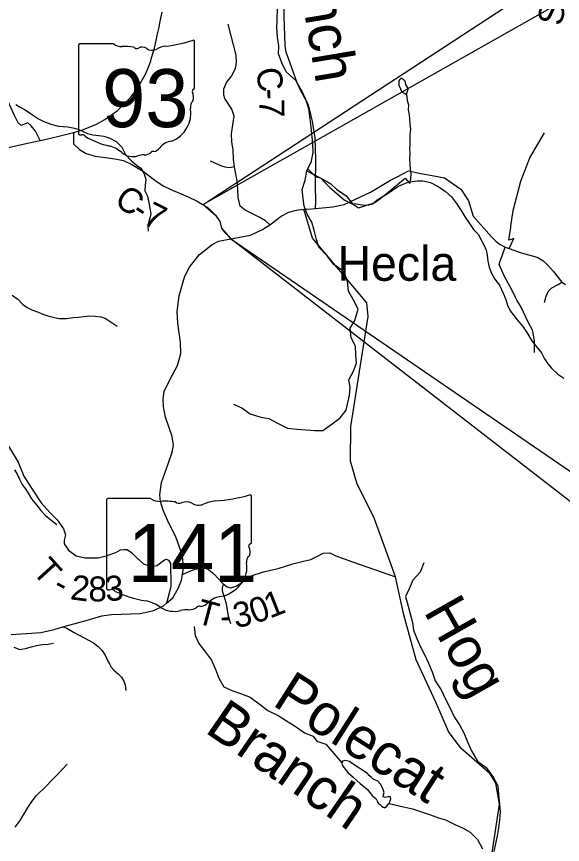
# Model space of a CAD drawing. Extents: x 0 to 34, y 0 to 22.
# Drawn here: x 4.209 to 5.45, y 15.517 to 17.398 of the extents above; entities that cross this region are included whole.
import ezdxf

# ---------------------------------------------------------------- set-up
doc = ezdxf.new("R2010")
doc.units = 0
for name, color, linetype in [('GM_X_County_Road', 7, 'Continuous'), ('GM_X_County_Road_Text', 7, 'Continuous'), ('GM_X_Minor_Lake', 7, 'Continuous'), ('GM_X_Minor_River', 7, 'Continuous'), ('GM_X_Minor_River_Text', 7, 'Continuous'), ('GM_X_State_Location', 7, 'Continuous'), ('GM_X_State_Route', 7, 'Continuous'), ('GM_X_State_Shield', 7, 'Continuous'), ('GM_X_Township_Road', 7, 'Continuous'), ('GM_X_Township_Road_Text', 7, 'Continuous'), ('GM_X_Unincorporated_Text', 7, 'Continuous'), ('SH_Text', 7, 'Continuous')]:
    doc.layers.add(name, color=color, linetype=linetype)

msp = doc.modelspace()

# ---------------------------------------------------------------- linework, layer by layer
at = {"layer": 'GM_X_County_Road'}
for points in [[(4.8886, 16.9624), (4.8894, 16.9787), (4.8887, 17.0141), (4.8892, 17.0726), (4.8884, 17.1231), (4.8823, 17.1597), (4.875, 17.1887), (4.8711, 17.2013), (4.8646, 17.2132), (4.8547, 17.2313), (4.8468, 17.2482), (4.831, 17.2926), (4.8221, 17.3179), (4.8198, 17.3327), (4.8178, 17.3985), (4.8173, 17.4627), (4.8096, 17.494), (4.7965, 17.5369), (4.7918, 17.5617), (4.7849, 17.5918), (4.7834, 17.6281)], [(4.2627, 17.1168), (4.257, 17.1291), (4.2524, 17.1378), (4.2427, 17.15), (4.2346, 17.1567), (4.2201, 17.1513), (4.2127, 17.1571), (4.2036, 17.1755), (4.1895, 17.207), (4.1712, 17.2541), (4.1524, 17.3111), (4.1244, 17.385), (4.1095, 17.4154)], [(4.2627, 17.1168), (4.2802, 17.1208), (4.3117, 17.128), (4.3389, 17.135)], [(4.3389, 17.135), (4.339, 17.1096), (4.352, 17.0964), (4.3677, 17.087), (4.388, 17.0816), (4.4115, 17.0785), (4.4326, 17.0754), (4.4522, 17.0712), (4.4713, 17.062), (4.4975, 17.0467), (4.5233, 17.0271), (4.5427, 17.0142), (4.5599, 17.0055), (4.599, 16.9891), (4.62, 16.9791), (4.6451, 16.9642), (4.6614, 16.9475), (4.6713, 16.9325), (4.6755, 16.9179), (4.681, 16.9095), (4.6884, 16.9017), (4.6965, 16.8937)], [(4.1518, 17.0918), (4.1671, 17.0954), (4.194, 17.1014), (4.211, 17.1054), (4.2342, 17.1105), (4.2627, 17.1168)], [(4.7848, 16.9253), (4.7877, 16.9272), (4.8111, 16.9451), (4.8283, 16.9539), (4.8458, 16.9589), (4.8625, 16.9605)], [(4.8625, 16.9605), (4.87, 16.9612), (4.8886, 16.9624)], [(5.2892, 15.4883), (5.3073, 15.6088), (5.2985, 15.6568), (5.2855, 15.6781), (5.2197, 15.7355), (5.1913, 15.7742), (5.1621, 15.8408), (5.1173, 15.9369), (5.0899, 16.0394), (5.0709, 16.1252), (5.042, 16.2049), (5.0212, 16.2608), (4.9838, 16.3357), (4.9681, 16.3879), (4.9688, 16.4668), (5.0088, 16.717), (5.0052, 16.7481), (4.8823, 16.8951), (4.8625, 16.9605)], [(4.6965, 16.8937), (4.7043, 16.8952), (4.7411, 16.9014), (4.7682, 16.9143), (4.7848, 16.9253)]]:
    msp.add_lwpolyline(points, dxfattribs=at)
at = {"layer": 'GM_X_Minor_Lake'}
for points in [[(5.0832, 17.2583), (5.0802, 17.2553), (5.0779, 17.2522), (5.0782, 17.2462), (5.0782, 17.2416), (5.0812, 17.2367), (5.0846, 17.2283), (5.0956, 17.2214)], [(5.0956, 17.2214), (5.0998, 17.2332), (5.0986, 17.2362), (5.0941, 17.2438), (5.0923, 17.2514), (5.0873, 17.256), (5.0832, 17.2583)], [(4.9721, 15.7016), (4.9661, 15.7058), (4.9627, 15.7066), (4.9551, 15.7081), (4.9498, 15.707), (4.949, 15.701), (4.9509, 15.6953), (4.9622, 15.6808), (4.9743, 15.6705), (4.9905, 15.6557), (5.0064, 15.6431), (5.0173, 15.6287), (5.0215, 15.6256), (5.0268, 15.6214), (5.0298, 15.6153), (5.0313, 15.6112), (5.0366, 15.6073), (5.0381, 15.6058), (5.0389, 15.6043), (5.0423, 15.6024), (5.0438, 15.602), (5.046, 15.6009), (5.051, 15.6043), (5.054, 15.6088), (5.0559, 15.6107)], [(5.0559, 15.6107), (5.0601, 15.6213), (5.059, 15.6258), (5.0537, 15.6255), (5.0472, 15.624), (5.0427, 15.6259), (5.0431, 15.6305), (5.045, 15.6358), (5.0424, 15.6426), (5.0393, 15.649), (5.0363, 15.6547), (5.0303, 15.6612), (5.0197, 15.6658), (5.0159, 15.6692), (5.0106, 15.6738), (5.0069, 15.6784), (4.9721, 15.7016)]]:
    msp.add_lwpolyline(points, dxfattribs=at)
at = {"layer": 'GM_X_Minor_River'}
for points in [[(4.7023, 16.5179), (4.7212, 16.5095), (4.7405, 16.4958), (4.7643, 16.4885), (4.7825, 16.4851), (4.8025, 16.4748), (4.8252, 16.4634), (4.846, 16.4607), (4.8668, 16.4591), (4.8865, 16.458), (4.9058, 16.4583), (4.9267, 16.4728), (4.9445, 16.4868), (4.9585, 16.5039), (4.9662, 16.5381), (4.9677, 16.5556), (4.9647, 16.5731), (4.975, 16.5929), (4.9822, 16.6108), (4.9804, 16.6302), (4.9801, 16.6499), (4.9699, 16.6682), (4.9673, 16.6903), (4.9779, 16.7078), (4.9856, 16.7336), (4.9743, 16.7557), (4.9637, 16.7743), (4.9619, 16.7964), (4.9536, 16.8188), (4.9305, 16.8352), (4.915, 16.855), (4.8962, 16.8744), (4.8909, 16.8919), (4.886, 16.9129), (4.8808, 16.9311), (4.8695, 16.9498), (4.8631, 16.9677), (4.8605, 16.9848), (4.8586, 17.0053), (4.8655, 17.0266), (4.8693, 17.0476), (4.88, 17.07), (4.8838, 17.0902), (4.8827, 17.1084), (4.8816, 17.1255), (4.879, 17.1469), (4.8764, 17.1651), (4.8734, 17.1887), (4.8666, 17.2097), (4.8587, 17.2283), (4.8444, 17.2531), (4.8225, 17.2732), (4.8119, 17.2934), (4.8048, 17.314), (4.8056, 17.3319), (4.8022, 17.3513), (4.8011, 17.3737), (4.8016, 17.3909), (4.8024, 17.4167)], [(5.093, 17.0309), (5.1034, 17.0191), (5.1057, 17.0301), (5.1061, 17.0411), (5.105, 17.0518), (5.1043, 17.0624), (5.1035, 17.0745), (5.1043, 17.0882), (5.1036, 17.0985), (5.104, 17.1079), (5.1041, 17.1303), (5.1052, 17.1428), (5.1037, 17.1542), (5.103, 17.166), (5.1023, 17.1755), (5.1, 17.1865), (5.1008, 17.1968), (5.0982, 17.207), (5.0971, 17.2169), (5.0956, 17.2214)], [(4.2073, 17.199), (4.2172, 17.1926), (4.2289, 17.1869), (4.2406, 17.1785), (4.2595, 17.1664), (4.2716, 17.16), (4.2871, 17.1539), (4.3049, 17.1497), (4.3154, 17.149), (4.3256, 17.1482), (4.3408, 17.1452), (4.351, 17.1418), (4.3608, 17.1376), (4.3706, 17.1331), (4.3823, 17.1296), (4.3963, 17.1281), (4.408, 17.127), (4.4216, 17.1221), (4.436, 17.1145), (4.4485, 17.1016), (4.4572, 17.0853), (4.4704, 17.0705), (4.4817, 17.0606), (4.4916, 17.0542), (4.4995, 17.0409), (4.5029, 17.028), (4.5018, 17.0155), (4.5006, 17.0026), (4.5067, 16.9901), (4.5101, 16.9753), (4.5131, 16.9597), (4.5142, 16.9491), (4.5116, 16.9381), (4.5078, 16.924), (4.5082, 16.9111)], [(4.8693, 17.0476), (4.9104, 17.0263), (4.924, 17.0183), (4.9365, 17.0066), (4.9486, 16.9978), (4.9584, 16.991), (4.9731, 16.9728), (4.9864, 16.9641), (5.0219, 16.9755), (5.0366, 16.985), (5.093, 17.0309)], [(4.8717, 17.0525), (4.8896, 17.0344), (4.9002, 17.0317), (4.9119, 17.0202), (4.9217, 17.01), (4.9323, 17.0008), (4.9432, 16.9909), (4.9542, 16.9821), (4.9697, 16.9734), (4.9807, 16.9726), (4.9958, 16.9706), (5.0083, 16.9698), (5.0185, 16.9732), (5.0287, 16.9819), (5.0428, 16.9902), (5.0541, 16.9973), (5.064, 17.0037), (5.0776, 17.0132), (5.0936, 17.0199), (5.1034, 17.0226), (5.1208, 17.0252), (5.1329, 17.0255), (5.15, 17.0213), (5.1662, 17.0132), (5.1832, 17.0018), (5.1979, 16.9888), (5.2093, 16.9736), (5.2202, 16.9576), (5.2292, 16.9424), (5.2387, 16.928), (5.2481, 16.9147), (5.259, 16.9036), (5.2647, 16.8922), (5.2715, 16.8797), (5.2771, 16.8675), (5.279, 16.8561), (5.2808, 16.8424), (5.2838, 16.8292), (5.2887, 16.8151), (5.2966, 16.8018), (5.3068, 16.7881), (5.3155, 16.7702), (5.3215, 16.7554), (5.3256, 16.7429), (5.3316, 16.7296), (5.3395, 16.7189), (5.3475, 16.7094), (5.3599, 16.6946), (5.3693, 16.6809), (5.3807, 16.6619), (5.392, 16.6471), (5.4022, 16.6345), (5.4093, 16.6208), (5.4169, 16.6094), (5.4252, 16.5999), (5.4395, 16.5862), (5.4531, 16.5767)], [(4.1993, 16.7653), (4.2122, 16.7562), (4.2231, 16.7452), (4.2337, 16.7377), (4.2443, 16.7323), (4.2568, 16.7274), (4.267, 16.7233), (4.2802, 16.7187), (4.2953, 16.7145), (4.3059, 16.7126), (4.3225, 16.7127), (4.3384, 16.7146), (4.3505, 16.7157), (4.3619, 16.7168), (4.3762, 16.7184), (4.3883, 16.718), (4.4012, 16.7161), (4.411, 16.7131), (4.4242, 16.7044), (4.4382, 16.6953)], [(4.2049, 16.3686), (4.2106, 16.3591), (4.2159, 16.3473), (4.2223, 16.3356), (4.2287, 16.3261), (4.2355, 16.3159), (4.2435, 16.303), (4.2544, 16.2889), (4.2646, 16.2764), (4.2744, 16.2654), (4.2873, 16.2548), (4.3005, 16.2446)], [(5.1353, 16.1573), (5.1269, 16.1364), (5.1098, 16.1178), (5.1014, 16.0981), (5.0934, 16.0806), (5.0994, 16.0589), (5.104, 16.0414), (5.1092, 16.0216), (5.1114, 16.0045), (5.119, 15.9851), (5.1276, 15.9661), (5.1367, 15.949), (5.1453, 15.9296), (5.154, 15.9098), (5.1611, 15.8889), (5.1747, 15.8691), (5.1841, 15.8478), (5.1943, 15.8284), (5.2037, 15.8075), (5.2165, 15.7892), (5.226, 15.7709), (5.2343, 15.7504), (5.2433, 15.7302), (5.2572, 15.7067), (5.2765, 15.6922), (5.2927, 15.6701), (5.3029, 15.6507), (5.3048, 15.631), (5.307, 15.6093), (5.3088, 15.5914), (5.3073, 15.5732), (5.305, 15.5553), (5.3019, 15.537), (5.2977, 15.5199), (5.2942, 15.5017)], [(4.6129, 16.0126), (4.6155, 15.9925), (4.6234, 15.9738), (4.6389, 15.9544), (4.6525, 15.9365), (4.6623, 15.9133), (4.669, 15.8951), (4.6807, 15.8757), (4.6985, 15.8673), (4.7208, 15.8593), (4.7405, 15.852), (4.7579, 15.8395), (4.7805, 15.8216), (4.8036, 15.8105), (4.8229, 15.7983), (4.8425, 15.7862), (4.8637, 15.7709), (4.8834, 15.7637), (4.8921, 15.7524), (4.9125, 15.7456), (4.9215, 15.7343), (4.9487, 15.7026), (4.9487, 15.7026)], [(4.2029, 15.9654), (4.2169, 15.9605), (4.2324, 15.9636), (4.2426, 15.9662), (4.2551, 15.9696), (4.2676, 15.9719), (4.2808, 15.9727), (4.2933, 15.9746)], [(4.2063, 15.5567), (4.2172, 15.5718), (4.2229, 15.5813), (4.2289, 15.5908), (4.2361, 15.6033), (4.2441, 15.6151), (4.2539, 15.6276), (4.277, 15.6507), (4.2894, 15.6636), (4.3015, 15.6754), (4.3129, 15.6879), (4.3246, 15.7)], [(5.0559, 15.6107), (5.089, 15.603), (5.1093, 15.5985), (5.1297, 15.5917), (5.1501, 15.5849), (5.1682, 15.5781), (5.1842, 15.5733), (5.2054, 15.563), (5.2232, 15.5554), (5.2406, 15.5455), (5.2568, 15.5283), (5.2681, 15.5074)]]:
    msp.add_lwpolyline(points, dxfattribs=at)
at = {"layer": 'GM_X_State_Route'}
for points in [[(4.5147, 17.2991), (4.5193, 17.3144), (4.5225, 17.3266), (4.5265, 17.3444), (4.5297, 17.3594), (4.5332, 17.3742), (4.5351, 17.3842), (4.5375, 17.3946), (4.5405, 17.4088)], [(4.3389, 17.135), (4.358, 17.1405), (4.3745, 17.1468), (4.3912, 17.1542), (4.4097, 17.1645), (4.4246, 17.1742), (4.4389, 17.1851), (4.4555, 17.2014), (4.4689, 17.2154), (4.4823, 17.2336), (4.4905, 17.2462), (4.5024, 17.2679), (4.509, 17.2837), (4.5144, 17.2981), (4.5147, 17.2991)], [(4.2627, 17.1168), (4.2802, 17.1208), (4.3117, 17.128), (4.3389, 17.135)], [(4.1518, 17.0918), (4.1671, 17.0954), (4.194, 17.1014), (4.211, 17.1054), (4.2342, 17.1105), (4.2627, 17.1168)], [(4.8886, 16.9624), (4.9284, 16.9659), (4.9539, 16.9716), (5.0141, 16.9998), (5.0592, 17.0268), (5.0744, 17.034), (5.1001, 17.048), (5.1279, 17.0422), (5.1541, 17.037), (5.1824, 17.0317), (5.2191, 17.0066), (5.2364, 16.9798), (5.2473, 16.9451), (5.289, 16.8981), (5.2992, 16.8871), (5.3084, 16.8808), (5.3199, 16.8743), (5.3291, 16.8717), (5.3563, 16.8616), (5.3927, 16.8515), (5.4058, 16.8439), (5.4159, 16.8344), (5.429, 16.8203), (5.4486, 16.7949), (5.4574, 16.7893)], [(4.7848, 16.9253), (4.7877, 16.9272), (4.8111, 16.9451), (4.8283, 16.9539), (4.8458, 16.9589), (4.8625, 16.9605)], [(4.8625, 16.9605), (4.87, 16.9612), (4.8886, 16.9624)], [(4.6965, 16.8937), (4.7043, 16.8952), (4.7411, 16.9014), (4.7682, 16.9143), (4.7848, 16.9253)], [(4.1968, 15.9947), (4.2431, 15.9978), (4.2647, 15.999), (4.2944, 16.0061), (4.3148, 16.0118), (4.3727, 16.0279), (4.4031, 16.0365), (4.4251, 16.0396), (4.4903, 16.0423), (4.5214, 16.0486), (4.5431, 16.0596), (4.5504, 16.0659), (4.5643, 16.0779), (4.5764, 16.0989), (4.5839, 16.1181), (4.5864, 16.131), (4.5889, 16.1469), (4.5863, 16.1742), (4.5718, 16.2139), (4.5524, 16.254), (4.5426, 16.2769), (4.5365, 16.2964), (4.5349, 16.3116), (4.5384, 16.34), (4.5538, 16.3822), (4.563, 16.4086), (4.5659, 16.4241), (4.5628, 16.4446), (4.548, 16.4885), (4.5435, 16.5125), (4.5427, 16.5299), (4.5448, 16.5462), (4.5582, 16.5748), (4.575, 16.606), (4.5826, 16.6332), (4.5819, 16.6579), (4.5762, 16.702), (4.5743, 16.7282), (4.5787, 16.7637), (4.5908, 16.806), (4.6018, 16.8286), (4.6253, 16.8578), (4.6537, 16.8809), (4.6682, 16.8882), (4.6965, 16.8937)]]:
    msp.add_lwpolyline(points, dxfattribs=at)
at = {"layer": 'GM_X_State_Shield'}
for p, q in [((4.3502, 17.3331), (4.3502, 17.133)), ((4.43, 17.3365), (4.3528, 17.3365)), ((4.6138, 17.2368), (4.6138, 17.3415)), ((4.6138, 17.2368), (4.6138, 17.2368)), ((4.4138, 16.2997), (4.4138, 16.0996)), ((4.5135, 16.3032), (4.417, 16.3032)), ((4.7434, 16.2035), (4.7434, 16.3082)), ((4.7433, 16.2035), (4.7434, 16.2035))]:
    msp.add_line(p, q, dxfattribs=at)
for centre, radius, start, end in [((4.5199, 17.6094), 0.2796, 275.8445, 288.9065), ((4.6109, 17.3419), 0.00294, 351.8621, 97.738), ((4.3532, 17.3335), 0.00305, 98.1301, 188.1301), ((4.4484, 17.3598), 0.0296, 231.6195, 271.1119), ((4.4582, 17.2242), 0.1064, 80.4867, 94.9883), ((4.4823, 17.3345), 0.00855, 219.7921, 297.1024), ((4.4949, 17.3114), 0.0178, 54.4667, 119.1411), ((4.5178, 17.3431), 0.0214, 233.8562, 294.8282), ((4.5556, 17.2754), 0.0563, 97.3462, 120.7689), ((4.6131, 17.2291), 0.00454, 107.944, 210.337), ((4.6107, 17.2364), 0.00314, 289.6038, 7.7341), ((4.5843, 17.2159), 0.0273, 340.033, 23.6496), ((4.6243, 17.193), 0.0198, 136.8065, 186.9296), ((4.5356, 17.1797), 0.0699, 292.3089, 8.9858), ((4.3532, 17.1325), 0.00308, 171.9584, 258.3066), ((4.3537, 17.153), 0.0235, 267.339, 280.6039), ((4.3585, 17.1214), 0.00848, 29.7484, 93.2717), ((4.4655, 17.3012), 0.2019, 240.4129, 257.1985), ((4.4053, 17.0431), 0.0632, 47.1842, 75.836), ((4.5165, 17.1136), 0.0226, 282.8732, 323.2771), ((4.5651, 17.0768), 0.0383, 94.4031, 142.5768), ((4.4737, 17.1204), 0.0401, 230.7004, 286.2918), ((4.4968, 17.0512), 0.0329, 85.6951, 111.2099), ((4.4998, 17.1054), 0.0214, 268.777, 315.5493), ((4.5191, 17.0861), 0.00601, 65.7517, 132.6484)]:
    msp.add_arc(centre, radius, start, end, dxfattribs=at)
for centre, major_axis, start_param, end_param in [((4.6259, 16.576), (0.3495, 0), 4.814394, 5.042369), ((4.7397, 16.3086), (0.00367, 0), 6.141152, 7.989035), ((4.4175, 16.3002), (0.00382, 0), 1.712693, 3.28349), ((4.5365, 16.3264), (0.037, 0), 4.042523, 4.731795), ((4.5488, 16.1908), (0.133, 0), 1.404758, 1.657858), ((4.579, 16.3012), (0.0107, 0), 3.836095, 5.185415), ((4.5947, 16.2781), (0.0222, 0), 0.950623, 2.079405), ((4.6233, 16.3098), (0.0267, 0), 4.081561, 5.145723), ((4.6705, 16.2421), (0.0703, 0), 1.699011, 2.107814), ((4.7425, 16.1958), (0.00568, 0), 1.883978, 3.671073), ((4.7394, 16.2031), (0.00393, 0), 5.05454, 6.418171), ((4.7064, 16.1825), (0.0341, 0), 5.934695, 6.695948), ((4.7565, 16.1597), (0.0248, 0), 2.387724, 3.262537), ((4.6455, 16.1463), (0.0874, 0), 5.101752, 6.440018), ((4.4176, 16.0992), (0.00385, 0), 3.00124, 4.508301), ((4.4182, 16.1197), (0.0294, 0), 4.665946, 4.897461), ((4.4242, 16.0881), (0.0106, 0), 0.519207, 1.627899), ((4.558, 16.2679), (0.2524, 0), 4.195997, 4.488961), ((4.4828, 16.0097), (0.079, 0), 0.823519, 1.323587), ((4.6217, 16.0802), (0.0282, 0), 4.937069, 5.64225), ((4.6824, 16.0434), (0.0479, 0), 1.647645, 2.488434), ((4.5682, 16.0871), (0.0501, 0), 4.026481, 4.996735), ((4.5971, 16.0179), (0.0412, 0), 1.495662, 1.94098), ((4.6008, 16.0721), (0.0267, 0), 4.691044, 5.507374), ((4.6249, 16.0527), (0.00752, 0), 1.147584, 2.315152)]:
    msp.add_ellipse(centre, major_axis=major_axis, ratio=0.8, start_param=start_param, end_param=end_param, dxfattribs=at)
at = {"layer": 'GM_X_Township_Road'}
msp.add_line((4.973, 16.1598), (5.0709, 16.1252), dxfattribs=at)
for points in [[(4.7848, 16.9253), (4.7754, 16.9345), (4.761, 16.9426), (4.7429, 16.9515), (4.7289, 16.9588), (4.7172, 16.9679), (4.7132, 16.987), (4.7125, 17.006), (4.7104, 17.025), (4.7056, 17.0527), (4.705, 17.0569), (4.7023, 17.074), (4.7013, 17.0949), (4.6988, 17.1136), (4.6978, 17.1322), (4.701, 17.1523), (4.7037, 17.1724), (4.6989, 17.1884), (4.6828, 17.2121), (4.6802, 17.2197), (4.6802, 17.2341), (4.6868, 17.2489), (4.6986, 17.2637), (4.7067, 17.2815), (4.7095, 17.294), (4.7084, 17.3107), (4.6903, 17.3808)], [(5.3325, 16.9189), (5.333, 16.9221), (5.3381, 16.958), (5.3555, 17.0248), (5.3763, 17.0775), (5.4092, 17.1339)], [(4.705, 17.0569), (4.6931, 17.0551), (4.6836, 17.0563), (4.6757, 17.0586), (4.6636, 17.064), (4.65, 17.0702)], [(5.3316, 16.8912), (5.3284, 16.8901), (5.3325, 16.9189)], [(5.3291, 16.8717), (5.3396, 16.8939), (5.3316, 16.8912)], [(5.3436, 16.7603), (5.3351, 16.7775), (5.3181, 16.8079), (5.3065, 16.8352), (5.3084, 16.8436), (5.3134, 16.8546), (5.3199, 16.8743)], [(5.4092, 16.7491), (5.4128, 16.7628), (5.418, 16.7735), (5.4263, 16.7824), (5.4403, 16.7894), (5.4486, 16.7949)], [(5.3827, 16.6827), (5.3822, 16.6856), (5.3722, 16.704), (5.356, 16.7381), (5.3465, 16.7543), (5.3436, 16.7603)], [(5.3867, 16.6348), (5.3864, 16.6615), (5.3827, 16.6827)], [(4.172, 16.4522), (4.1747, 16.4478), (4.1929, 16.4186), (4.2126, 16.3863), (4.2256, 16.3545), (4.2435, 16.3271), (4.2652, 16.2933), (4.2848, 16.2716), (4.3019, 16.2553), (4.3158, 16.2349), (4.3204, 16.2207), (4.3172, 16.209), (4.3177, 16.2003), (4.3243, 16.1909)], [(4.3243, 16.1909), (4.3259, 16.1886), (4.3276, 16.186), (4.3444, 16.1732), (4.3648, 16.1686), (4.3951, 16.1687), (4.413, 16.1732), (4.4348, 16.1811), (4.4459, 16.1866), (4.4535, 16.1879), (4.4607, 16.1878), (4.4708, 16.1808), (4.4834, 16.168), (4.4979, 16.1547), (4.511, 16.1503), (4.5209, 16.1497), (4.5289, 16.1514), (4.5373, 16.1581), (4.5454, 16.1644), (4.5504, 16.1654), (4.5549, 16.1634), (4.5593, 16.1557), (4.5597, 16.1041), (4.5559, 16.0882), (4.5504, 16.0659)], [(4.5864, 16.131), (4.6017, 16.1378), (4.6143, 16.1428), (4.6299, 16.1451), (4.6379, 16.145), (4.6454, 16.1425), (4.658, 16.132), (4.6792, 16.1096), (4.6881, 16.1025), (4.696, 16.1001), (4.7098, 16.1051), (4.7294, 16.1184), (4.7428, 16.1279), (4.7703, 16.1365), (4.8042, 16.1441), (4.8374, 16.1552), (4.8614, 16.1608), (4.8782, 16.1646), (4.8935, 16.1726), (4.9065, 16.1795), (4.9217, 16.18), (4.9348, 16.1732), (4.973, 16.1598)], [(4.6792, 16.1096), (4.6763, 16.1001), (4.6769, 16.0933), (4.6805, 16.0822), (4.6847, 16.0669), (4.6871, 16.0547), (4.6901, 16.0361), (4.6954, 16.0192)], [(4.3148, 16.0118), (4.3234, 16.0085), (4.3402, 15.999), (4.3841, 15.9753), (4.3949, 15.9675), (4.403, 15.9586), (4.4104, 15.9474), (4.4154, 15.9367), (4.4202, 15.9279), (4.4246, 15.9202), (4.4301, 15.9136), (4.4409, 15.9043), (4.4476, 15.8977), (4.453, 15.8885), (4.4559, 15.8804), (4.4579, 15.8675)]]:
    msp.add_lwpolyline(points, dxfattribs=at)
at = {"layer": 'SH_Text'}
for points in [[(4.6333, 16.9712), (5.8902, 17.7932), (5.8902, 17.6825)], [(4.6965, 16.8937), (5.9375, 16.0436), (5.9375, 15.9329)]]:
    msp.add_lwpolyline(points, close=True, dxfattribs=at)
msp.add_lwpolyline([(4.6333, 16.9712), (4.6614, 16.9475), (4.6713, 16.9325), (4.6755, 16.9179), (4.6965, 16.8937)], dxfattribs=at)

# ---------------------------------------------------------------- texts
at = {"layer": 'GM_X_County_Road_Text'}
for s, rotation, p in [('S', 80.7083, (5.4492, 17.3759)), ('C', 279.9596, (4.7525, 17.278)), ('-', 271.8581, (4.7604, 17.2341)), ('7', 270.7702, (4.7611, 17.2111)), ('C', 325.3351, (4.4284, 16.9734)), ('7', 332.7624, (4.4931, 16.9297)), ('-', 326.0871, (4.4675, 16.9464))]:
    msp.add_text(s, height=0.0568, rotation=rotation, dxfattribs=at).set_placement(p)
at = {"layer": 'GM_X_Minor_River_Text'}
for s, height, rotation, p in [('Branch', 0.09475, 279.4884, (4.8243, 17.64)), ('Hog', 0.09468, 299.4951, (5.1333, 16.047)), ('Polecat', 0.09469, 327.4947, (4.7881, 15.8354)), ('Branch', 0.09469, 325.4951, (4.6345, 15.774))]:
    msp.add_text(s, height=height, rotation=rotation, dxfattribs=at).set_placement(p)
at = {"layer": 'GM_X_State_Location'}
for s, p in [('s', (4.479, 17.2197)), ('r', (4.479, 17.2197)), ('s', (4.5749, 16.1864)), ('r', (4.5748, 16.1864))]:
    msp.add_text(s, height=0.000189, dxfattribs=at).set_placement(p)
for s, p in [('93', (4.4313, 17.2059)), ('141', (4.508, 16.1726))]:
    msp.add_text(s, height=0.000189, rotation=0, dxfattribs=at).set_placement(p)
at = {"layer": 'GM_X_State_Shield'}
for s, p in [('93', (4.4038, 17.1471)), ('141', (4.4623, 16.1137))]:
    msp.add_text(s, height=0.13184, dxfattribs=at).set_placement(p)
at = {"layer": 'GM_X_Township_Road_Text'}
for s, rotation, p in [('T', 312.2603, (4.2427, 16.1367)), ('2', 352.3507, (4.3296, 16.0747)), ('8', 0.003, (4.3725, 16.0695)), ('3', 4.7263, (4.4126, 16.0697)), ('-', 332.458, (4.2885, 16.092)), ('1', 21.5291, (4.7853, 16.0303)), ('T', 345.0927, (4.6148, 16.0209)), ('3', 10.7065, (4.7067, 16.009)), ('0', 19.3519, (4.7501, 16.0179)), ('-', 0.1046, (4.672, 16.0079))]:
    msp.add_text(s, height=0.0568, rotation=rotation, dxfattribs=at).set_placement(p)
at = {"layer": 'GM_X_Unincorporated_Text'}
msp.add_text('Hecla', height=0.07898, rotation=0, dxfattribs=at).set_placement((4.9388, 16.7981))

doc.saveas('drawing.dxf')
